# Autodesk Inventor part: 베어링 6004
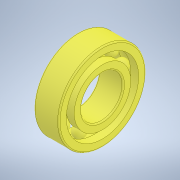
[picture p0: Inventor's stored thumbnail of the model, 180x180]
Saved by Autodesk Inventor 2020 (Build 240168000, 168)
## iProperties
Created: 2024-04
Part Number: 베어링 6004
Material: 강철, 연강
Description: 깊은 그루브 볼 베어링
Document SubType Name: Modeling
Designer: oem
Density: 7.85 g/cm^3
Appearance: 기본값
Author: jhkim
Sending System: Autodesk Inventor 2025
Preprocessor: ST-DEVELOPER v20
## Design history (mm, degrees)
feature "Solid1"
feature "Solid1:1"
feature "Solid1:2"
feature "Solid1:3"
feature "Solid1:4"
feature "Solid1:5"
feature "Solid1:6"
feature "Solid1:7"
feature "Solid1:8"
feature "Solid1:9"
feature "Solid1:10"
node "솔리드1"
node "솔리드2"
node "솔리드3"
node "솔리드4"
node "솔리드5"
node "솔리드6"
node "솔리드7"
node "솔리드8"
node "솔리드9"
node "솔리드10"
node "솔리드11"
